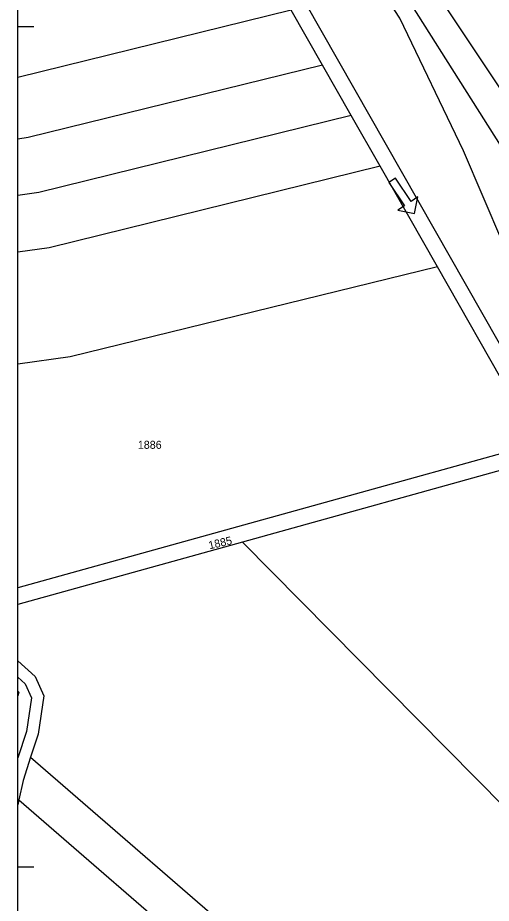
# Model space of a CAD drawing. Extents: x -601739 to -601440, y -1201912 to -1200862.
# Drawn here: x -601738.8 to -601620.6, y -1201711.4 to -1201490.1 of the extents above; entities that cross this region are included whole.
import ezdxf

# ---------------------------------------------------------------- set-up
doc = ezdxf.new("R2010")
doc.units = 0
for name, color, linetype in [('Hranice parcel', 7, 'Continuous'), ('Parcelní čísla', 7, 'Continuous'), ('u_prijezd', 7, 'Continuous'), ('x_rám', 7, 'Continuous')]:
    doc.layers.add(name, color=color, linetype=linetype)

msp = doc.modelspace()

# ---------------------------------------------------------------- linework, layer by layer
at = {"layer": 'Hranice parcel'}
for p, q in [((-601662.72, -1201501.91), (-601670.53, -1201488.18)), ((-601655.53, -1201514.55), (-601662.72, -1201501.91)), ((-601648.34, -1201527.2), (-601655.53, -1201514.55)), ((-601634.01, -1201552.38), (-601648.34, -1201527.2)), ((-601611.88, -1201591.29), (-601634.01, -1201552.38)), ((-601682.69, -1201621.14), (-601738.83, -1201636.73))]:
    msp.add_line(p, q, dxfattribs=at)
for points in [[(-601738.83, -1201327.85), (-601736.9, -1201330.72), (-601724.62, -1201347.71), (-601680.65, -1201411.14), (-601639.4, -1201476.17), (-601592.66, -1201546.3), (-601570.68, -1201592.44)], [(-601738.83, -1201338.87), (-601723.67, -1201361.08), (-601684.22, -1201417.67), (-601645.08, -1201479.64), (-601599.95, -1201551.04), (-601577.91, -1201595.98)], [(-601602.51, -1201597.25), (-601612.76, -1201557.83), (-601627.47, -1201523.39), (-601643.42, -1201490.21), (-601659.52, -1201465.35), (-601686.41, -1201425.71), (-601706.32, -1201392.22), (-601738.83, -1201347.06)], [(-601602.51, -1201597.25), (-601606.61, -1201592.45), (-601674.97, -1201472.32), (-601697.36, -1201436.46), (-601738.84, -1201377.24)], [(-601602.51, -1201597.25), (-601606.61, -1201592.45), (-601674.97, -1201472.32), (-601697.36, -1201436.46), (-601738.83, -1201377.25)], [(-601670.53, -1201488.18), (-601738.83, -1201505.02)], [(-601662.72, -1201501.91), (-601736.21, -1201520.04), (-601738.83, -1201520.4)], [(-601655.53, -1201514.55), (-601733.58, -1201533.81), (-601738.83, -1201534.53)], [(-601648.34, -1201527.2), (-601730.95, -1201547.58), (-601738.83, -1201548.66)], [(-601634.01, -1201552.38), (-601725.71, -1201574.86), (-601738.83, -1201576.71)], [(-601611.88, -1201591.29), (-601614.69, -1201598.11), (-601738.83, -1201632.58)], [(-601603.77, -1201605.53), (-601612.65, -1201601.69), (-601682.69, -1201621.14)], [(-601682.69, -1201621.14), (-601595.16, -1201709.69), (-601577.81, -1201727.24)], [(-601738.83, -1201650.83), (-601734.51, -1201654.77), (-601732.29, -1201659.59), (-601733.74, -1201669.16), (-601735.62, -1201674.91)], [(-601738.83, -1201654.89), (-601736.98, -1201656.58), (-601735.39, -1201660.03), (-601736.67, -1201668.46), (-601738.83, -1201675.08)], [(-601738.83, -1201658.37), (-601738.53, -1201658.62), (-601738.83, -1201659.6)], [(-601735.62, -1201674.91), (-601737.52, -1201680.74), (-601738.57, -1201685.58)], [(-601735.62, -1201674.91), (-601675.26, -1201727.24)], [(-601738.57, -1201685.58), (-601738.83, -1201686.79)], [(-601738.57, -1201685.58), (-601690.52, -1201727.24)]]:
    msp.add_lwpolyline(points, dxfattribs=at)
at = {"layer": 'u_prijezd'}
msp.add_lwpolyline([(-601643.89, -1201538.21), (-601639.73, -1201539.04), (-601638.9, -1201534.88), (-601640.56, -1201535.99), (-601644.45, -1201530.17), (-601646.12, -1201531.28), (-601642.23, -1201537.1), (-601643.89, -1201538.21)], dxfattribs=at)
at = {"layer": 'x_rám'}
for p, q in [((-601734.8, -1201492.35), (-601738.84, -1201492.35)), ((-601734.8, -1201702.35), (-601738.84, -1201702.35))]:
    msp.add_line(p, q, dxfattribs=at)
msp.add_lwpolyline([(-601441.84, -1200862.35), (-601441.84, -1201912.35), (-601738.84, -1201912.35), (-601738.84, -1200862.35)], close=True, dxfattribs=at)

# ---------------------------------------------------------------- texts
at = {"layer": 'Parcelní čísla'}
msp.add_text('1886', height=2, dxfattribs=at).set_placement((-601708.84, -1201597.83))
msp.add_text('1885', height=2, rotation=13, dxfattribs=at).set_placement((-601690.94, -1201622.96))

doc.saveas('drawing.dxf')
